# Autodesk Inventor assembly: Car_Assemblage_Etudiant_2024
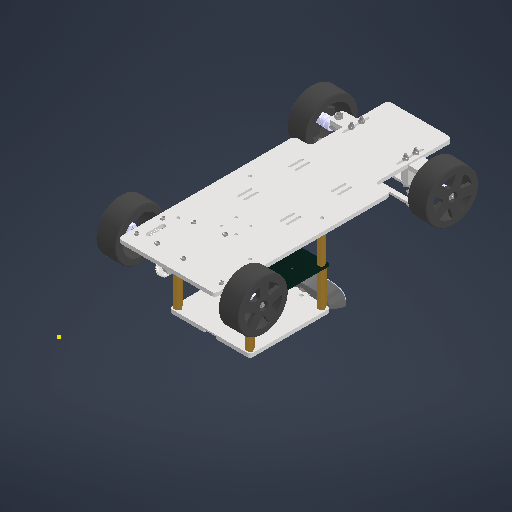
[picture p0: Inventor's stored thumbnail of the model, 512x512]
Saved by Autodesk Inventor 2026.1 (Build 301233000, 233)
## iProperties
Created: 2023-10
Part Number: Car_Assemblage_Etudiant_2024
Document SubType Name: Assembly
Designer: baince
Mass: 835.359 g
Surface Area: 2295.89 cm^2
Volume: 721.463 cm^3
Density: 1.15787 g/cm^3
Author: baince
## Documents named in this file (35)
- C:\Users\baince\Documents\Cours\Ateliers ROB\Autodesk Inventor\Car_Assemblage\Export_Etudiant_2024\Car_Assemblage_Etudiant_2024.iam
- C:\Users\baince\Documents\Cours\Ateliers ROB\Autodesk Inventor\Car_Assemblage\Export_Etudiant_2024\chassis.ipt
- C:\Users\baince\Documents\Cours\Ateliers ROB\Autodesk Inventor\Car_Assemblage\Export_Etudiant_2024\support_avant.ipt
- C:\Users\baince\Documents\Cours\Ateliers ROB\Autodesk Inventor\Car_Assemblage\Export_Etudiant_2024\support_arriere_gauche.ipt
- C:\Users\baince\Documents\Cours\Ateliers ROB\Autodesk Inventor\Car_Assemblage\Export_Etudiant_2024\moteur_brushless.ipt
- C:\Users\baince\Documents\Cours\Ateliers ROB\Autodesk Inventor\Car_Assemblage\Export_Etudiant_2024\adaptateur roue.ipt
- C:\Users\baince\Documents\Cours\Ateliers ROB\Autodesk Inventor\Car_Assemblage\Export_Etudiant_2024\adaptateur_brushless.ipt
- C:\Users\baince\Documents\Cours\Ateliers ROB\Autodesk Inventor\Car_Assemblage\Export_Etudiant_2024\roue.ipt
- C:\Users\baince\Documents\Cours\Ateliers ROB\Autodesk Inventor\Car_Assemblage\Export_Etudiant_2024\biellette_servo_moteur.ipt
- C:\Users\baince\Documents\Cours\Ateliers ROB\Autodesk Inventor\Car_Assemblage\Export_Etudiant_2024\support_servo_moteur.ipt
- C:\Users\baince\Documents\Cours\Ateliers ROB\Autodesk Inventor\Car_Assemblage\Export_Etudiant_2024\SUPPORT_MOTEUR_BRUSHLESS2.IPT
- C:\Users\baince\Documents\Cours\Ateliers ROB\Autodesk Inventor\Car_Assemblage\Export_Etudiant_2024\corps_servo_moteur.ipt
- C:\Users\baince\Documents\Cours\Ateliers ROB\Autodesk Inventor\Car_Assemblage\Export_Etudiant_2024\batterie.ipt
- C:\Users\baince\Documents\Cours\Ateliers ROB\Autodesk Inventor\Car_Assemblage\Export_Etudiant_2024\roulement_6_19.ipt
- C:\Users\baince\Documents\Cours\Ateliers ROB\Autodesk Inventor\Car_Assemblage\Export_Etudiant_2024\pignon_15_dents.ipt
- C:\Users\baince\Documents\Cours\Ateliers ROB\Autodesk Inventor\Car_Assemblage\Export_Etudiant_2024\pignon_32_dents.ipt
- C:\Users\baince\Documents\Cours\Ateliers ROB\Autodesk Inventor\Car_Assemblage\Export_Etudiant_2024\axe_taraude_m4.ipt
- C:\Users\baince\Documents\Cours\Ateliers ROB\Autodesk Inventor\Car_Assemblage\Export_Etudiant_2024\roulement_4_13.ipt
- C:\Users\baince\Documents\Cours\Ateliers ROB\Autodesk Inventor\Car_Assemblage\Export_Etudiant_2024\ISO 4032 - M4 - ISO.ipt
- C:\Users\baince\Documents\Cours\Ateliers ROB\Autodesk Inventor\Car_Assemblage\Export_Etudiant_2024\ANSI B18.16.3M - Property Class 5 and 10 - Metric M3 x 0.5 Type de métal.ipt
- C:\Users\baince\Documents\Cours\Ateliers ROB\Autodesk Inventor\Car_Assemblage\Export_Etudiant_2024\ANSI B18.3.1M - M3x0,5 x 30(1).ipt
- C:\Users\baince\Documents\Cours\Ateliers ROB\Autodesk Inventor\Car_Assemblage\Export_Etudiant_2024\ISO 4762 - M4 x 30ISO.ipt
- C:\Users\baince\Documents\Cours\Ateliers ROB\Autodesk Inventor\Car_Assemblage\Export_Etudiant_2024\ISO 7089 - 4 - 140 HV(1).ipt
- C:\Users\baince\Documents\Cours\Ateliers ROB\Autodesk Inventor\Car_Assemblage\Export_Etudiant_2024\ISO 4762 - M4 x 35ISO.ipt
- C:\Users\baince\Documents\Cours\Ateliers ROB\Autodesk Inventor\Car_Assemblage\Export_Etudiant_2024\SKF623.ipt
- C:\Users\baince\Documents\Cours\Ateliers ROB\Autodesk Inventor\Car_Assemblage\Export_Etudiant_2024\ISO 7089 - 6 - 140 HV(1).ipt
- C:\Users\baince\Documents\Cours\Ateliers ROB\Autodesk Inventor\Car_Assemblage\Export_Etudiant_2024\ANSI B18.3.1M - M3x0,5 x 35(1).ipt
- C:\Users\baince\Documents\Cours\Ateliers ROB\Autodesk Inventor\Car_Assemblage\Export_Etudiant_2024\ISO 7089 - 3 - 140 HV(1).ipt
- C:\Users\baince\Documents\Cours\Ateliers ROB\Autodesk Inventor\Car_Assemblage\Export_Etudiant_2024\EN ISO 7045 - M3 x 14 - 4.8 - Z(2).ipt
- C:\Users\baince\Documents\Cours\Ateliers ROB\Autodesk Inventor\Car_Assemblage\Export_Etudiant_2024\VisM3-16.ipt
- C:\Users\baince\Documents\Cours\Ateliers ROB\Autodesk Inventor\Car_Assemblage\Export_Etudiant_2024\support_avant_MIR2.ipt
- C:\Users\baince\Documents\Cours\Ateliers ROB\Autodesk Inventor\Car_Assemblage\Export_Etudiant_2024\ESSIEU_ARRIERE.IPT
- C:\Users\baince\Documents\Cours\Ateliers ROB\Autodesk Inventor\Car_Assemblage\Export_Etudiant_2024\barre_direction.ipt
- C:\Users\baince\Documents\Cours\Ateliers ROB\Autodesk Inventor\Car_Assemblage\Export_Etudiant_2024\pcb_assembly.iam
- C:\Users\baince\Documents\Cours\Ateliers ROB\Autodesk Inventor\Car_Assemblage\Export_Etudiant_2024\sensors_haut.iam
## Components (120 placed, 34 different names)
1. chassis:1 — Placage:1, Placage:5, Placage:19, Affleurement:1, Affleurement:2, Placage:21, Placage:22, Placage:23, Placage:26, Placage:27, Placage:28, Placage:66, Placage:68, Placage:70, Placage:72, Logement:57, Logement:58, Logement:59, Logement:60, Logement:61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
2. ESSIEU ARRIERE:1
3. support_avant:1 — Placage:1, Placage:3, Placage:4, Placage:5, Placage:7, Logement:30, Logement:84, Placage:87, Placage:89
4. moteur_brushless:1 — Placage:29, Placage:30, Placage:31, Logement:12
5. adaptateur roue:1 — Placage:43, Placage:44, Placage:45, Logement:18
6. adaptateur_brushless:1
7. roue:1 — Placage:42, Placage:46, Placage:47, Logement:39
8. roue:2 — Placage:41, Placage:48, Placage:49, Logement:41
9. roue:3 — Placage:40, Placage:50, Placage:51, Logement:37
10. roue:4 — Placage:43, Placage:44, Placage:45, Logement:35
11. support_arriere_gauche:2 — Placage:21, Placage:22, Placage:23, Placage:36, Placage:38, Logement:65, Logement:69
12. biellette_servo_moteur:1 — Placage:15, Placage:16, Placage:101, Placage:116
13. support_servo_moteur:1 — Placage:3, Placage:4, Placage:7, Placage:12, Placage:13, Placage:14, Logement:43, Logement:45, Logement:47, Logement:49
14. SUPPORT_MOTEUR_BRUSHLESS2:1 — Placage:26, Placage:27, Placage:28, Placage:32, Placage:33, Placage:34, Logement:66, Logement:70, Logement:73, Logement:74, Logement:75, Logement:76
15. corps_servo_moteur:1 — Placage:12, Placage:13, Placage:14, Placage:15, Placage:16
16. batterie:1 — Placage:19, Affleurement:1, Affleurement:2
17. roulement_6_19:1 — Logement:27
18. roulement_6_19:2 — Placage:36, Placage:38
19. adaptateur roue:2 — Placage:42, Placage:46, Placage:47
20. adaptateur roue:3 — Placage:41, Placage:48, Placage:49, Placage:115
21. adaptateur roue:4 — Placage:40, Placage:50, Placage:51, Logement:19
22. pignon_15_dents:1 — Logement:12, Tangente:1
23. pignon_32_dents:1 — Tangente:2
24. axe_taraude_m4:1 — Logement:25, Placage:63
25. roulement_4_13:1 — Logement:6, Placage:92, Placage:113
26. roulement_4_13:2 — Logement:3, Placage:114
27. roulement_4_13:3 — Logement:8, Placage:90
28. roulement_4_13:4 — Logement:10, Placage:109, Placage:110
29. ISO 4032 M4:1 — Logement:31
30. Ecrou hexagonal autofreiné - Acier Métrique Property Class 5 and 10 - Metric M3 x 0.5 Type de métal:1 — Logement:52
31. Vis à tête forgée - Métrique M3x0,5 x 30:1 — Logement:22, Placage:62
32. ISO 4762 M4 x 30:1 — Logement:2, Placage:111, Placage:112
33. ISO 4762 M4 x 30:2 — Logement:7, Placage:108, Placage:109
34. ISO 7089 4:1 — Logement:30, Logement:31
35. ISO 4762 M4 x 35:1 — Logement:83
36. ISO 4762 M4 x 35:2 — Logement:85
37. ISO 7089 4:2 — Logement:2, Logement:3
38. ISO 7089 4:3 — Logement:6, Logement:18
39. ISO 7089 4:4 — Logement:10, Logement:19
40. ISO 7089 4:5 — Logement:7, Logement:8
41. roulement_6_19:3 — Logement:25, Placage:81
42. SKF- roulements à une rangée de billes SKF623:1 — Logement:22, Logement:54
43. ISO 7089 6:1 — Logement:29, Placage:64, Placage:107
44. ISO 7089 6:2 — Logement:27
45. pignon_32_dents:2 — Placage:63, Placage:64, Tangente:1, Placage:81, Placage:107
46. pignon_15_dents:2 — Placage:62, Logement:29, Tangente:2
47. ISO 4032 M4:2 — Logement:32
48. ISO 4032 M4:3 — Logement:34
49. ISO 4032 M4:4 — Logement:36
50. ISO 4032 M4:5 — Logement:38
51. ISO 4032 M4:6 — Logement:40
52. ISO 7089 4:6 — Logement:34, Logement:35
53. ISO 7089 4:7 — Logement:36, Logement:37
54. ISO 7089 4:8 — Logement:38, Logement:39
55. ISO 7089 4:9 — Logement:40, Logement:41
56. ISO 7089 4:10 — Logement:32, Logement:96
57. Vis à tête forgée - Métrique M3x0,5 x 35:1 — Logement:42, Placage:69
58. Vis à tête forgée - Métrique M3x0,5 x 35:2 — Logement:44, Placage:71
59. Vis à tête forgée - Métrique M3x0,5 x 35:3 — Logement:48, Placage:65, Placage:76
60. Vis à tête forgée - Métrique M3x0,5 x 35:4 — Logement:46, Placage:67, Placage:79
61. Ecrou hexagonal autofreiné - Acier Métrique Property Class 5 and 10 - Metric M3 x 0.5 Type de métal:2 — Logement:50
62. Ecrou hexagonal autofreiné - Acier Métrique Property Class 5 and 10 - Metric M3 x 0.5 Type de métal:3 — Logement:51
63. Ecrou hexagonal autofreiné - Acier Métrique Property Class 5 and 10 - Metric M3 x 0.5 Type de métal:4 — Logement:53
64. ISO 7089 3:1 — Logement:44, Logement:45
65. ISO 7089 3:2 — Logement:46, Logement:47
66. ISO 7089 3:3 — Logement:52, Placage:71, Placage:72
67. ISO 7089 3:4 — Logement:53, Placage:65, Placage:66
68. ISO 7089 3:5 — Logement:48, Logement:49
69. ISO 7089 3:6 — Logement:54, Logement:55
70. ISO 7089 3:7 — Logement:50, Placage:69, Placage:70
71. ISO 7089 3:8 — Logement:42, Logement:43
72. ISO 7089 3:9 — Logement:51, Placage:67, Placage:68
73. ISO 7089 3:10 — Logement:55, Logement:56
74. ISO 7089 3:11 — Logement:56
75. NF EN ISO 7045 - Z M3 x 14 - 4.8 - Z:1 — Logement:60
76. NF EN ISO 7045 - Z M3 x 14 - 4.8 - Z:2 — Logement:59
77. NF EN ISO 7045 - Z M3 x 14 - 4.8 - Z:3 — Logement:58
78. NF EN ISO 7045 - Z M3 x 14 - 4.8 - Z:4 — Logement:57
79. NF EN ISO 7045 - Z M3 x 14 - 4.8 - Z:5 — Logement:61
80. NF EN ISO 7045 - Z M3 x 14 - 4.8 - Z:6 — Logement:62
81. NF EN ISO 7045 - Z M3 x 14 - 4.8 - Z:7 — Logement:63
82. NF EN ISO 7045 - Z M3 x 14 - 4.8 - Z:8 — Logement:64
83. Ecrou hexagonal autofreiné - Acier Métrique Property Class 5 and 10 - Metric M3 x 0.5 Type de métal:5 — Logement:65
84. Ecrou hexagonal autofreiné - Acier Métrique Property Class 5 and 10 - Metric M3 x 0.5 Type de métal:6
85. Ecrou hexagonal autofreiné - Acier Métrique Property Class 5 and 10 - Metric M3 x 0.5 Type de métal:7
86. Ecrou hexagonal autofreiné - Acier Métrique Property Class 5 and 10 - Metric M3 x 0.5 Type de métal:8 — Logement:66
87. Ecrou hexagonal autofreiné - Acier Métrique Property Class 5 and 10 - Metric M3 x 0.5 Type de métal:9 — Logement:75
88. Ecrou hexagonal autofreiné - Acier Métrique Property Class 5 and 10 - Metric M3 x 0.5 Type de métal:10 — Logement:69
89. Ecrou hexagonal autofreiné - Acier Métrique Property Class 5 and 10 - Metric M3 x 0.5 Type de métal:11 — Logement:70
90. Ecrou hexagonal autofreiné - Acier Métrique Property Class 5 and 10 - Metric M3 x 0.5 Type de métal:12 — Logement:73
91. Ecrou hexagonal autofreiné - Acier Métrique Property Class 5 and 10 - Metric M3 x 0.5 Type de métal:13
92. Ecrou hexagonal autofreiné - Acier Métrique Property Class 5 and 10 - Metric M3 x 0.5 Type de métal:14
93. Ecrou hexagonal autofreiné - Acier Métrique Property Class 5 and 10 - Metric M3 x 0.5 Type de métal:15 — Logement:74
94. Ecrou hexagonal autofreiné - Acier Métrique Property Class 5 and 10 - Metric M3 x 0.5 Type de métal:16 — Logement:76
95. NF EN ISO 7045 - Z M3 x 14 - 4.8 - Z:9 — Logement:77
96. NF EN ISO 7045 - Z M3 x 14 - 4.8 - Z:10 — Logement:78
97. NF EN ISO 7045 - Z M3 x 14 - 4.8 - Z:11 — Logement:80
98. NF EN ISO 7045 - Z M3 x 14 - 4.8 - Z:12 — Logement:79
99. VisM3-16:1 — Logement:88
100. VisM3-16:2 — Logement:89
101. Ecrou hexagonal autofreiné - Acier Métrique Property Class 5 and 10 - Metric M3 x 0.5 Type de métal:17 — Logement:87
102. Ecrou hexagonal autofreiné - Acier Métrique Property Class 5 and 10 - Metric M3 x 0.5 Type de métal:18
103. ISO 7089 3:13
104. ISO 7089 3:14 — Logement:87
105. ISO 7089 3:15 — Logement:89, Placage:100
106. ISO 7089 4:11 — Logement:83, Logement:84
107. ISO 7089 4:12 — Logement:85, Logement:95
108. ISO 7089 3:16 — Logement:88, Placage:99
109. support_avant_MIR2:1
110. barre_direction:1 — Placage:99, Placage:100, Placage:101, Placage:116
111. ISO 7089 4:13 — Placage:88
112. ISO 7089 4:14 — Placage:85
113. ISO 7089 4:15 — Placage:87
114. ISO 7089 4:16 — Placage:89
115. ISO 7089 4:17 — Placage:91, Placage:108, Placage:110
116. ISO 7089 4:18 — Placage:90, Placage:91
117. ISO 7089 4:19 — Placage:93, Placage:111, Placage:114
118. ISO 7089 4:20 — Placage:92, Placage:93, Placage:112, Placage:113
119. pcb_assembly:1 [sub-assembly] — Placage:102, Placage:103, Placage:104, Placage:105, Placage:106
120. sensors_haut:1 [sub-assembly] — Placage:105, Placage:106
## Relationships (151: Mate 80, Insert 67, Flush 2, Tangent 2)
- Placage:1 [Mate]: chassis:1 ↔ support_avant:1
- Placage:3 [Mate]: support_avant:1 ↔ support_servo_moteur:1
- Placage:4 [Mate]: support_avant:1 ↔ support_servo_moteur:1
- Placage:5 [Mate]: chassis:1 ↔ support_avant:1
- Placage:7 [Mate]: support_avant:1 ↔ support_servo_moteur:1
- Placage:12 [Mate]: support_servo_moteur:1 ↔ corps_servo_moteur:1
- Placage:13 [Mate]: support_servo_moteur:1 ↔ corps_servo_moteur:1
- Placage:14 [Mate]: support_servo_moteur:1 ↔ corps_servo_moteur:1
- Placage:15 [Mate]: biellette_servo_moteur:1 ↔ corps_servo_moteur:1
- Placage:16 [Mate]: biellette_servo_moteur:1 ↔ corps_servo_moteur:1
- Placage:19 [Mate]: chassis:1 ↔ batterie:1
- Affleurement:1 [Flush]: chassis:1 ↔ batterie:1
- Affleurement:2 [Flush]: chassis:1 ↔ batterie:1
- Placage:21 [Mate]: chassis:1 ↔ support_arriere_gauche:2
- Placage:22 [Mate]: chassis:1 ↔ support_arriere_gauche:2
- Placage:23 [Mate]: chassis:1 ↔ support_arriere_gauche:2
- Placage:26 [Mate]: chassis:1 ↔ SUPPORT_MOTEUR_BRUSHLESS2:1
- Placage:27 [Mate]: chassis:1 ↔ SUPPORT_MOTEUR_BRUSHLESS2:1
- Placage:28 [Mate]: chassis:1 ↔ SUPPORT_MOTEUR_BRUSHLESS2:1
- Placage:29 [Mate]: moteur_brushless:1
- Placage:30 [Mate]: moteur_brushless:1
- Placage:31 [Mate]: moteur_brushless:1
- Placage:32 [Mate]: SUPPORT_MOTEUR_BRUSHLESS2:1
- Placage:33 [Mate]: SUPPORT_MOTEUR_BRUSHLESS2:1
- Placage:34 [Mate]: SUPPORT_MOTEUR_BRUSHLESS2:1
- Placage:36 [Mate]: support_arriere_gauche:2 ↔ roulement_6_19:2
- Placage:38 [Mate]: support_arriere_gauche:2 ↔ roulement_6_19:2
- Placage:40 [Mate]: roue:3 ↔ adaptateur roue:4
- Placage:41 [Mate]: roue:2 ↔ adaptateur roue:3
- Placage:42 [Mate]: roue:1 ↔ adaptateur roue:2
- Placage:43 [Mate]: adaptateur roue:1 ↔ roue:4
- Placage:44 [Mate]: adaptateur roue:1 ↔ roue:4
- Placage:45 [Mate]: adaptateur roue:1 ↔ roue:4
- Placage:46 [Mate]: roue:1 ↔ adaptateur roue:2
- Placage:47 [Mate]: roue:1 ↔ adaptateur roue:2
- Placage:48 [Mate]: roue:2 ↔ adaptateur roue:3
- Placage:49 [Mate]: roue:2 ↔ adaptateur roue:3
- Placage:50 [Mate]: roue:3 ↔ adaptateur roue:4
- Placage:51 [Mate]: roue:3 ↔ adaptateur roue:4
- Logement:2 [Insert]: ISO 4762 M4 x 30:1 ↔ ISO 7089 4:2
- Logement:3 [Insert]: roulement_4_13:2 ↔ ISO 7089 4:2
- Logement:6 [Insert]: roulement_4_13:1 ↔ ISO 7089 4:3
- Logement:7 [Insert]: ISO 4762 M4 x 30:2 ↔ ISO 7089 4:5
- Logement:8 [Insert]: roulement_4_13:3 ↔ ISO 7089 4:5
- Logement:10 [Insert]: roulement_4_13:4 ↔ ISO 7089 4:4
- Logement:12 [Insert]: moteur_brushless:1 ↔ pignon_15_dents:1
- Logement:18 [Insert]: adaptateur roue:1 ↔ ISO 7089 4:3
- Logement:19 [Insert]: adaptateur roue:4 ↔ ISO 7089 4:4
- Logement:22 [Insert]: Vis à tête forgée - Métrique M3x0,5 x 30:1 ↔ SKF- roulements à une rangée de billes SKF623:1
- Logement:25 [Insert]: axe_taraude_m4:1 ↔ roulement_6_19:3
- Logement:27 [Insert]: roulement_6_19:1 ↔ ISO 7089 6:2
- Placage:62 [Mate]: Vis à tête forgée - Métrique M3x0,5 x 30:1 ↔ pignon_15_dents:2
- Logement:29 [Insert]: ISO 7089 6:1 ↔ pignon_15_dents:2
- Placage:63 [Mate]: axe_taraude_m4:1 ↔ pignon_32_dents:2
- Placage:64 [Mate]: ISO 7089 6:1 ↔ pignon_32_dents:2
- Tangente:1: pignon_15_dents:1 ↔ pignon_32_dents:2
- Tangente:2: pignon_32_dents:1 ↔ pignon_15_dents:2
- Logement:30 [Insert]: support_avant:1 ↔ ISO 7089 4:1
- Logement:31 [Insert]: ISO 4032 M4:1 ↔ ISO 7089 4:1
- Logement:32 [Insert]: ISO 4032 M4:2 ↔ ISO 7089 4:10
- Logement:34 [Insert]: ISO 4032 M4:3 ↔ ISO 7089 4:6
- Logement:35 [Insert]: roue:4 ↔ ISO 7089 4:6
- Logement:36 [Insert]: ISO 4032 M4:4 ↔ ISO 7089 4:7
- Logement:37 [Insert]: roue:3 ↔ ISO 7089 4:7
- Logement:38 [Insert]: ISO 4032 M4:5 ↔ ISO 7089 4:8
- Logement:39 [Insert]: roue:1 ↔ ISO 7089 4:8
- Logement:40 [Insert]: ISO 4032 M4:6 ↔ ISO 7089 4:9
- Logement:41 [Insert]: roue:2 ↔ ISO 7089 4:9
- Logement:42 [Insert]: Vis à tête forgée - Métrique M3x0,5 x 35:1 ↔ ISO 7089 3:8
- Logement:43 [Insert]: support_servo_moteur:1 ↔ ISO 7089 3:8
- Logement:44 [Insert]: Vis à tête forgée - Métrique M3x0,5 x 35:2 ↔ ISO 7089 3:1
- Logement:45 [Insert]: support_servo_moteur:1 ↔ ISO 7089 3:1
- Logement:46 [Insert]: Vis à tête forgée - Métrique M3x0,5 x 35:4 ↔ ISO 7089 3:2
- Logement:47 [Insert]: support_servo_moteur:1 ↔ ISO 7089 3:2
- Logement:48 [Insert]: Vis à tête forgée - Métrique M3x0,5 x 35:3 ↔ ISO 7089 3:5
- Logement:49 [Insert]: support_servo_moteur:1 ↔ ISO 7089 3:5
- Logement:50 [Insert]: Ecrou hexagonal autofreiné - Acier Métrique Property Class 5 and 10 - Metric M3 x 0.5 Type de métal:2 ↔ ISO 7089 3:7
- Logement:51 [Insert]: Ecrou hexagonal autofreiné - Acier Métrique Property Class 5 and 10 - Metric M3 x 0.5 Type de métal:3 ↔ ISO 7089 3:9
- Logement:52 [Insert]: Ecrou hexagonal autofreiné - Acier Métrique Property Class 5 and 10 - Metric M3 x 0.5 Type de métal:1 ↔ ISO 7089 3:3
- Logement:53 [Insert]: Ecrou hexagonal autofreiné - Acier Métrique Property Class 5 and 10 - Metric M3 x 0.5 Type de métal:4 ↔ ISO 7089 3:4
- Placage:65 [Mate]: Vis à tête forgée - Métrique M3x0,5 x 35:3 ↔ ISO 7089 3:4
- Placage:66 [Mate]: chassis:1 ↔ ISO 7089 3:4
- Placage:67 [Mate]: Vis à tête forgée - Métrique M3x0,5 x 35:4 ↔ ISO 7089 3:9
- Placage:68 [Mate]: chassis:1 ↔ ISO 7089 3:9
- Placage:69 [Mate]: Vis à tête forgée - Métrique M3x0,5 x 35:1 ↔ ISO 7089 3:7
- Placage:70 [Mate]: chassis:1 ↔ ISO 7089 3:7
- Placage:71 [Mate]: Vis à tête forgée - Métrique M3x0,5 x 35:2 ↔ ISO 7089 3:3
- Placage:72 [Mate]: chassis:1 ↔ ISO 7089 3:3
- Logement:54 [Insert]: SKF- roulements à une rangée de billes SKF623:1 ↔ ISO 7089 3:6
- Logement:55 [Insert]: ISO 7089 3:6 ↔ ISO 7089 3:10
- Logement:56 [Insert]: ISO 7089 3:10 ↔ ISO 7089 3:11
- Logement:57 [Insert]: chassis:1 ↔ NF EN ISO 7045 - Z M3 x 14 - 4.8 - Z:4
- Logement:58 [Insert]: chassis:1 ↔ NF EN ISO 7045 - Z M3 x 14 - 4.8 - Z:3
- Logement:59 [Insert]: chassis:1 ↔ NF EN ISO 7045 - Z M3 x 14 - 4.8 - Z:2
- Logement:60 [Insert]: chassis:1 ↔ NF EN ISO 7045 - Z M3 x 14 - 4.8 - Z:1
- Logement:61 [Insert]: chassis:1 ↔ NF EN ISO 7045 - Z M3 x 14 - 4.8 - Z:5
- Logement:62 [Insert]: chassis:1 ↔ NF EN ISO 7045 - Z M3 x 14 - 4.8 - Z:6
- Logement:63 [Insert]: chassis:1 ↔ NF EN ISO 7045 - Z M3 x 14 - 4.8 - Z:7
- Logement:64 [Insert]: chassis:1 ↔ NF EN ISO 7045 - Z M3 x 14 - 4.8 - Z:8
- Logement:65 [Insert]: support_arriere_gauche:2 ↔ Ecrou hexagonal autofreiné - Acier Métrique Property Class 5 and 10 - Metric M3 x 0.5 Type de métal:5
- Logement:66 [Insert]: SUPPORT_MOTEUR_BRUSHLESS2:1 ↔ Ecrou hexagonal autofreiné - Acier Métrique Property Class 5 and 10 - Metric M3 x 0.5 Type de métal:8
- Logement:69 [Insert]: support_arriere_gauche:2 ↔ Ecrou hexagonal autofreiné - Acier Métrique Property Class 5 and 10 - Metric M3 x 0.5 Type de métal:10
- Logement:70 [Insert]: SUPPORT_MOTEUR_BRUSHLESS2:1 ↔ Ecrou hexagonal autofreiné - Acier Métrique Property Class 5 and 10 - Metric M3 x 0.5 Type de métal:11
- Logement:73 [Insert]: SUPPORT_MOTEUR_BRUSHLESS2:1 ↔ Ecrou hexagonal autofreiné - Acier Métrique Property Class 5 and 10 - Metric M3 x 0.5 Type de métal:12
- Logement:74 [Insert]: SUPPORT_MOTEUR_BRUSHLESS2:1 ↔ Ecrou hexagonal autofreiné - Acier Métrique Property Class 5 and 10 - Metric M3 x 0.5 Type de métal:15
- Logement:75 [Insert]: SUPPORT_MOTEUR_BRUSHLESS2:1 ↔ Ecrou hexagonal autofreiné - Acier Métrique Property Class 5 and 10 - Metric M3 x 0.5 Type de métal:9
- Logement:76 [Insert]: SUPPORT_MOTEUR_BRUSHLESS2:1 ↔ Ecrou hexagonal autofreiné - Acier Métrique Property Class 5 and 10 - Metric M3 x 0.5 Type de métal:16
- Logement:77 [Insert]: NF EN ISO 7045 - Z M3 x 14 - 4.8 - Z:9
- Logement:78 [Insert]: NF EN ISO 7045 - Z M3 x 14 - 4.8 - Z:10
- Logement:79 [Insert]: NF EN ISO 7045 - Z M3 x 14 - 4.8 - Z:12
- Logement:80 [Insert]: NF EN ISO 7045 - Z M3 x 14 - 4.8 - Z:11
- Logement:83 [Insert]: ISO 4762 M4 x 35:1 ↔ ISO 7089 4:11
- Logement:84 [Insert]: support_avant:1 ↔ ISO 7089 4:11
- Logement:85 [Insert]: ISO 4762 M4 x 35:2 ↔ ISO 7089 4:12
- Logement:87 [Insert]: Ecrou hexagonal autofreiné - Acier Métrique Property Class 5 and 10 - Metric M3 x 0.5 Type de métal:17 ↔ ISO 7089 3:14
- Logement:88 [Insert]: VisM3-16:1 ↔ ISO 7089 3:16
- Logement:89 [Insert]: VisM3-16:2 ↔ ISO 7089 3:15
- Placage:74 [Mate]: chassis:1
- Placage:75 [Mate]: chassis:1
- Placage:76 [Mate]: Vis à tête forgée - Métrique M3x0,5 x 35:3
- Logement:95 [Insert]: ISO 7089 4:12
- Placage:79 [Mate]: Vis à tête forgée - Métrique M3x0,5 x 35:4
- Placage:80 [Mate]: chassis:1
- Logement:96 [Insert]: ISO 7089 4:10
- Placage:81 [Mate]: roulement_6_19:3 ↔ pignon_32_dents:2
- Placage:85 [Mate]: ISO 7089 4:14
- Placage:87 [Mate]: support_avant:1 ↔ ISO 7089 4:15
- Placage:88 [Mate]: ISO 7089 4:13
- Placage:89 [Mate]: support_avant:1 ↔ ISO 7089 4:16
- Placage:90 [Mate]: roulement_4_13:3 ↔ ISO 7089 4:18
- Placage:91 [Mate]: ISO 7089 4:17 ↔ ISO 7089 4:18
- Placage:92 [Mate]: roulement_4_13:1 ↔ ISO 7089 4:20
- Placage:93 [Mate]: ISO 7089 4:19 ↔ ISO 7089 4:20
- Placage:99 [Mate]: ISO 7089 3:16 ↔ barre_direction:1
- Placage:100 [Mate]: ISO 7089 3:15 ↔ barre_direction:1
- Placage:101 [Mate]: biellette_servo_moteur:1 ↔ barre_direction:1
- Placage:102 [Mate]: chassis:1 ↔ pcb_assembly:1
- Placage:103 [Mate]: chassis:1 ↔ pcb_assembly:1
- Placage:104 [Mate]: chassis:1 ↔ pcb_assembly:1
- Placage:105 [Mate]: pcb_assembly:1 ↔ sensors_haut:1
- Placage:106 [Mate]: pcb_assembly:1 ↔ sensors_haut:1
- Placage:107 [Mate]: ISO 7089 6:1 ↔ pignon_32_dents:2
- Placage:108 [Mate]: ISO 4762 M4 x 30:2 ↔ ISO 7089 4:17
- Placage:109 [Mate]: roulement_4_13:4 ↔ ISO 4762 M4 x 30:2
- Placage:110 [Mate]: roulement_4_13:4 ↔ ISO 7089 4:17
- Placage:111 [Mate]: ISO 4762 M4 x 30:1 ↔ ISO 7089 4:19
- Placage:112 [Mate]: ISO 4762 M4 x 30:1 ↔ ISO 7089 4:20
- Placage:113 [Mate]: roulement_4_13:1 ↔ ISO 7089 4:20
- Placage:114 [Mate]: roulement_4_13:2 ↔ ISO 7089 4:19
- Placage:115 [Mate]: adaptateur roue:3
- Placage:116 [Mate]: biellette_servo_moteur:1 ↔ barre_direction:1
## Named parameters: d185_d147 = 0
